Omron CX-Programmer project NewProject (CX-Programmer 9.35)

# PLC NewPLC1: CJ1M CPU22
I/O table (CPU CJ1M-CPU22): rack 0 slot 0 CJ1W-ETN21(ETN11Mode); rack 0 slot 1 CJ1W-SCU41-V1; rack 0 slot 2 CJ1W-ID211; rack 0 slot 3 CJ1W-OD212; rack 0 slot 4 CJ1W-ID261

## Program NewProgram1 (cyclic task 0)

### Section Section1

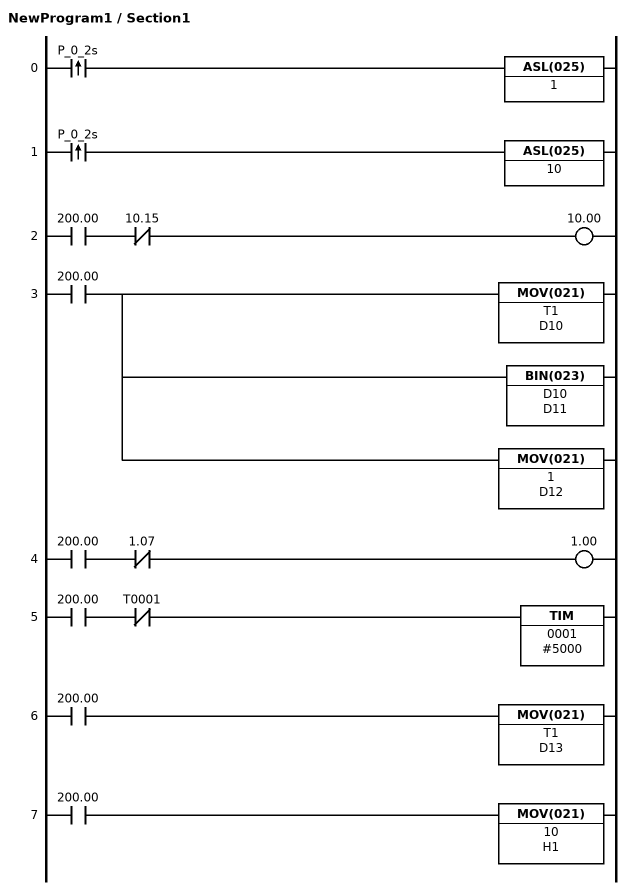
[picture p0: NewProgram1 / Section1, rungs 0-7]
; rung 0
@LD P_0_2s
ASL(025) 1
; rung 1
@LD P_0_2s
ASL(025) 10
; rung 2
LD 200.00
ANDNOT 10.15
OUT 10.00
; rung 3
LD 200.00
MOV(021) T1 D10
BIN(023) D10 D11
MOV(021) 1 D12
; rung 4
LD 200.00
ANDNOT 1.07
OUT 1.00
; rung 5
LD 200.00
ANDNOT T0001
TIM 0001 #5000
; rung 6
LD 200.00
MOV(021) T1 D13
; rung 7
LD 200.00
MOV(021) 10 H1
; rung 8
END(001)
; rung 9
END(001)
